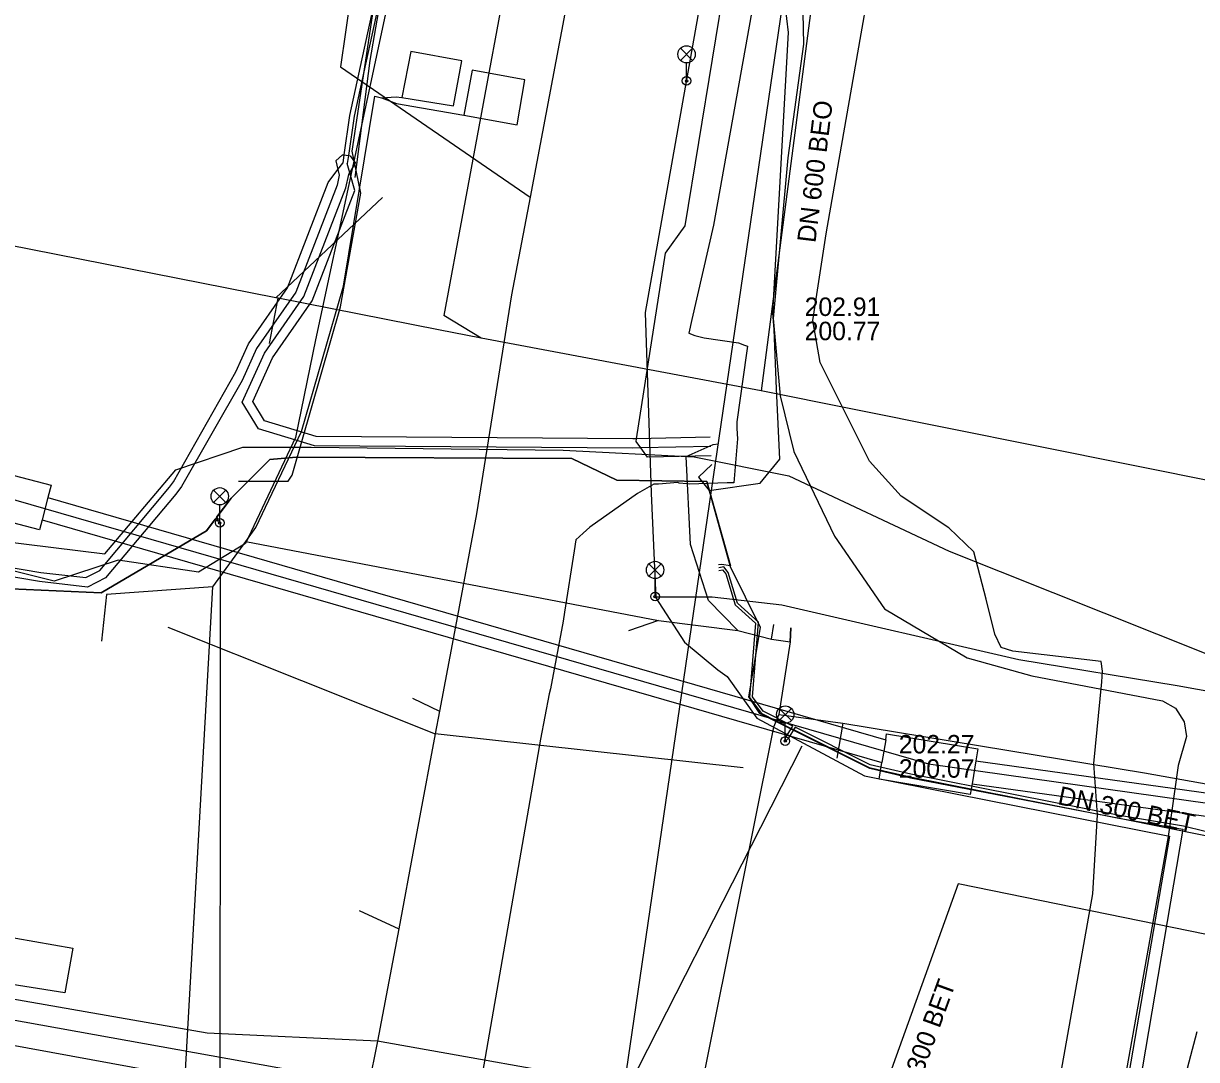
# Model space of a CAD drawing. Extents: x -596228 to -595156, y -1161235 to -1159373.
# Drawn here: x -595929.1 to -595878.3, y -1160323.7 to -1160278.8 of the extents above; entities that cross this region are included whole.
import ezdxf

# ---------------------------------------------------------------- set-up
doc = ezdxf.new("R2010")
doc.units = 0
for name, color, linetype in [('Vrstva 1', 7, 'Continuous'), ('Vrstva 10', 7, 'Continuous'), ('Vrstva 12', 7, 'Continuous'), ('Vrstva 14', 7, 'Continuous'), ('Vrstva 16', 7, 'Continuous'), ('Vrstva 19', 7, 'Continuous'), ('Vrstva 33', 7, 'Continuous'), ('Vrstva 4', 7, 'Continuous'), ('Vrstva 42', 7, 'Continuous'), ('Vrstva 44', 7, 'Continuous'), ('Vrstva 5', 7, 'Continuous'), ('Vrstva 53', 7, 'Continuous'), ('Vrstva 54', 7, 'Continuous'), ('Vrstva 55', 7, 'Continuous'), ('Vrstva 58', 7, 'Continuous'), ('Vrstva 9', 7, 'Continuous')]:
    doc.layers.add(name, color=color, linetype=linetype)

msp = doc.modelspace()

# ---------------------------------------------------------------- linework, layer by layer
at = {"layer": 'Vrstva 1'}
for p, q in [((-595903.46, -1160251.27), (-595910.91, -1160291.43)), ((-595894.35, -1160272.94), (-595897.18, -1160294.69)), ((-595913.57, -1160286.32), (-595918.179, -1160290.659)), ((-595918.462, -1160292.641), (-595918.081, -1160290.678)), ((-595909.29, -1160292.41), (-595910.91, -1160291.43)), ((-595897.18, -1160294.69), (-595909.29, -1160292.41)), ((-595854.43, -1160303.29), (-595897.18, -1160294.69)), ((-595922.85, -1160304.93), (-595911.286, -1160309.552)), ((-595897.96, -1160311.02), (-595911.286, -1160309.552)), ((-595888.65, -1160316.04), (-595892.47, -1160326.63)), ((-595888.649, -1160316.044), (-595892.47, -1160326.63)), ((-595871.84, -1160319.47), (-595888.65, -1160316.04)), ((-595871.843, -1160319.471), (-595888.65, -1160316.042)), ((-595914.57, -1160317.2), (-595912.866, -1160317.985))]:
    msp.add_line(p, q, dxfattribs=at)
msp.add_lwpolyline([(-595909.29, -1160292.41), (-595911.144, -1160292.045), (-595918.081, -1160290.678), (-595918.179, -1160290.659), (-595934.064, -1160287.531), (-595934.702, -1160287.405), (-595941.02, -1160286.161), (-595949.988, -1160284.394), (-595952.078, -1160283.983), (-595952.65, -1160283.87)], dxfattribs=at)
at = {"layer": 'Vrstva 10'}
for p, q in [((-595928.05, -1160299.31), (-595928.3, -1160300.28)), ((-595928.05, -1160299.31), (-595928.3, -1160300.28)), ((-595928.05, -1160299.31), (-595891.79, -1160309.8)), ((-595928.05, -1160299.31), (-595891.79, -1160309.8)), ((-595928.3, -1160300.28), (-595891.96, -1160310.79)), ((-595928.3, -1160300.28), (-595891.96, -1160310.79)), ((-595891.79, -1160309.8), (-595891.96, -1160310.79)), ((-595891.79, -1160309.8), (-595891.96, -1160310.79)), ((-595887.89, -1160310.72), (-595888.05, -1160311.71)), ((-595887.89, -1160310.72), (-595888.05, -1160311.71)), ((-595887.89, -1160310.72), (-595811.15, -1160321.35)), ((-595887.89, -1160310.72), (-595811.15, -1160321.35)), ((-595888.05, -1160311.71), (-595811.33, -1160322.33)), ((-595888.05, -1160311.71), (-595811.33, -1160322.33))]:
    msp.add_line(p, q, dxfattribs=at)
for points in [[(-595931.93, -1160298.34), (-595931.78, -1160297.77), (-595927.91, -1160298.77), (-595928.05, -1160299.31)], [(-595931.93, -1160298.34), (-595931.78, -1160297.77), (-595927.91, -1160298.77), (-595928.05, -1160299.31)], [(-595928.3, -1160300.28), (-595928.41, -1160300.71), (-595932.28, -1160299.7), (-595932.18, -1160299.31)], [(-595928.3, -1160300.28), (-595928.41, -1160300.71), (-595932.28, -1160299.7), (-595932.18, -1160299.31)], [(-595891.79, -1160309.8), (-595891.75, -1160309.54), (-595887.8, -1160310.2), (-595887.89, -1160310.72)], [(-595891.79, -1160309.8), (-595891.75, -1160309.54), (-595887.8, -1160310.2), (-595887.89, -1160310.72)], [(-595888.05, -1160311.71), (-595888.13, -1160312.17), (-595892.08, -1160311.51), (-595891.96, -1160310.79)], [(-595888.05, -1160311.71), (-595888.13, -1160312.17), (-595892.08, -1160311.51), (-595891.96, -1160310.79)]]:
    msp.add_lwpolyline(points, dxfattribs=at)
at = {"layer": 'Vrstva 12'}
msp.add_line((-595913.327, -1160277.82), (-595916.466, -1160292.479), dxfattribs=at)
for points in [[(-595916.466, -1160292.479), (-595917.33, -1160296.71), (-595919.49, -1160301.3), (-595921.53, -1160302.54), (-595925, -1160302.02), (-595927.78, -1160302.93), (-595932.98, -1160301.64), (-595934.44, -1160300.59), (-595934.41, -1160299.84), (-595933.92, -1160299.18)], [(-595930.09, -1160299.24), (-595889.94, -1160310.85), (-595809.314, -1160322.217)]]:
    msp.add_lwpolyline(points, dxfattribs=at)
at = {"layer": 'Vrstva 14'}
for points in [[(-595903.525, -1160327.591), (-595903.438, -1160327.11), (-595895.992, -1160276.218), (-595895.362, -1160271.913), (-595894.416, -1160266.829), (-595893.077, -1160257.958), (-595892.847, -1160256.335), (-595887.94, -1160223.167), (-595881.65, -1160186.81), (-595876.814, -1160159.541), (-595869.649, -1160117.522), (-595863.209, -1160078.856), (-595858.091, -1160048.124), (-595857.576, -1160045.207), (-595855.994, -1160045.422), (-595855.543, -1160042.523), (-595857.05, -1160042.292), (-595850.5, -1160006.311), (-595840.026, -1160007.969)], [(-595912.327, -1160326.199), (-595944.525, -1160320.296), (-595964.314, -1160316.668), (-595981.5, -1160313.518), (-595993.326, -1160311.35), (-595998.98, -1160310.314), (-596012.243, -1160307.882), (-596018.266, -1160306.788), (-596020.483, -1160306.371), (-596031.546, -1160304.536), (-596031.549, -1160304.535)]]:
    msp.add_lwpolyline(points, dxfattribs=at)
at = {"layer": 'Vrstva 16'}
msp.add_lwpolyline([(-595917.38, -1160324.14), (-595937.03, -1160320.6), (-595938.02, -1160320.43), (-595944.42, -1160319.31), (-595959.68, -1160316.64), (-595967.05, -1160315.3), (-595979.197, -1160313.085)], dxfattribs=at)
at = {"layer": 'Vrstva 19'}
msp.add_lwpolyline([(-595897.424, -1160277.35), (-595899.243, -1160287.517), (-595900.187, -1160291.609), (-595900.304, -1160292.198), (-595900.056, -1160292.292), (-595899.647, -1160292.397), (-595898.154, -1160292.619), (-595897.903, -1160292.711), (-595897.776, -1160292.755), (-595897.812, -1160293.055), (-595898.226, -1160296.041), (-595898.234, -1160296.33), (-595898.199, -1160296.768), (-595898.359, -1160298.672), (-595898.644, -1160298.671), (-595900.278, -1160298.736), (-595900.392, -1160298.713), (-595900.724, -1160298.687), (-595900.779, -1160298.661), (-595901.623, -1160298.727), (-595901.831, -1160298.727), (-595902.532, -1160299.138), (-595904.591, -1160300.602), (-595904.877, -1160300.858), (-595905.2, -1160301.147), (-595905.273, -1160301.62), (-595905.685, -1160304.282), (-595905.754, -1160304.662), (-595906.299, -1160307.601), (-595906.351, -1160307.82), (-595906.726, -1160309.776), (-595909.359, -1160324.873)], dxfattribs=at)
at = {"layer": 'Vrstva 33'}
for p, q in [((-595900.675, -1160279.855), (-595900.145, -1160280.385)), ((-595900.675, -1160280.385), (-595900.145, -1160279.855)), ((-595900.41, -1160281.27), (-595900.41, -1160280.495)), ((-595920.875, -1160298.995), (-595920.345, -1160299.525)), ((-595920.875, -1160299.525), (-595920.345, -1160298.995)), ((-595920.61, -1160300.41), (-595920.61, -1160299.635)), ((-595902.035, -1160302.185), (-595901.505, -1160302.715)), ((-595902.035, -1160302.715), (-595901.505, -1160302.185)), ((-595901.77, -1160303.6), (-595901.77, -1160302.825)), ((-595896.402, -1160308.444), (-595895.872, -1160308.974)), ((-595896.402, -1160308.974), (-595895.872, -1160308.444)), ((-595896.137, -1160309.859), (-595896.137, -1160309.084))]:
    msp.add_line(p, q, dxfattribs=at)
for centre, radius in [((-595900.41, -1160280.12), 0.375), ((-595900.41, -1160281.27), 0.19), ((-595900.41, -1160281.27), 0.05), ((-595920.61, -1160299.26), 0.375), ((-595920.61, -1160300.41), 0.19), ((-595920.61, -1160300.41), 0.05), ((-595901.77, -1160302.45), 0.375), ((-595901.77, -1160303.6), 0.19), ((-595901.77, -1160303.6), 0.05), ((-595896.137, -1160308.709), 0.375), ((-595896.137, -1160309.859), 0.19), ((-595896.137, -1160309.859), 0.05)]:
    msp.add_circle(centre, radius, dxfattribs=at)
at = {"layer": 'Vrstva 42'}
for p, q in [((-595919.369, -1160292.663), (-595917.68, -1160290.231)), ((-595917.324, -1160290.42), (-595919.02, -1160292.861)), ((-595918.67, -1160293.059), (-595916.968, -1160290.608)), ((-595918.321, -1160293.257), (-595916.612, -1160290.797)), ((-595899.257, -1160297.02), (-595899.038, -1160296.984)), ((-595925.509, -1160303.506), (-595925.725, -1160305.533)), ((-595920.903, -1160303.182), (-595925.509, -1160303.506)), ((-595901.62, -1160304.641), (-595902.915, -1160305.079)), ((-595896.735, -1160305.447), (-595896.634, -1160304.812)), ((-595895.931, -1160305.565), (-595895.894, -1160304.949)), ((-595893.65, -1160309.078), (-595893.899, -1160310.595))]:
    msp.add_line(p, q, dxfattribs=at)
for points in [[(-595899.339, -1160297.503), (-595902.099, -1160297.56), (-595902.383, -1160297.165), (-595902.586, -1160296.883), (-595902.568, -1160296.769), (-595901.316, -1160288.727), (-595900.471, -1160287.553), (-595898.687, -1160276.707), (-595898.101, -1160273.351), (-595895.17, -1160256.55), (-595893.577, -1160246.717), (-595892.781, -1160243.14), (-595887.556, -1160214.494), (-595883.249, -1160189.231), (-595883.208, -1160189), (-595882.655, -1160185.86), (-595879.849, -1160169.95), (-595878.786, -1160163.811), (-595878.313, -1160161.147), (-595878.278, -1160160.95), (-595875.884, -1160147.461), (-595871.512, -1160122.724)], [(-595899.318, -1160297.883), (-595899.891, -1160298.432), (-595899.423, -1160299.009), (-595897.224, -1160298.688), (-595896.375, -1160297.645), (-595896.521, -1160294.611), (-595896.622, -1160292.035), (-595896.678, -1160291.316), (-595895.995, -1160279.177), (-595896.207, -1160277.347), (-595896.845, -1160276.413), (-595898.101, -1160273.351), (-595898.174, -1160273.174), (-595898.37, -1160272.566), (-595895.372, -1160255.298), (-595894.03, -1160247.01), (-595893.153, -1160242.953), (-595888.976, -1160220.051), (-595884.001, -1160189.966)], [(-595918.504, -1160259.738), (-595913.263, -1160260.629), (-595911.808, -1160260.75), (-595911.519, -1160260.809), (-595911.298, -1160261.051), (-595910.768, -1160262.017), (-595910.821, -1160262.872), (-595911.242, -1160265.118), (-595912.672, -1160273.05), (-595914.792, -1160282.798), (-595915.041, -1160284.502), (-595915.041, -1160284.504), (-595915.091, -1160284.854)], [(-595918.537, -1160259.935), (-595913.288, -1160260.828), (-595911.837, -1160260.948), (-595911.623, -1160260.992), (-595911.462, -1160261.169), (-595910.972, -1160262.063), (-595911.019, -1160262.848), (-595911.438, -1160265.082), (-595912.868, -1160273.011), (-595914.988, -1160282.762), (-595915.239, -1160284.476), (-595915.239, -1160284.478), (-595915.289, -1160284.826)], [(-595913.609, -1160282.001), (-595912.971, -1160281.955), (-595912.73, -1160281.991), (-595910.501, -1160282.355), (-595910.13, -1160280.397), (-595912.345, -1160279.993), (-595912.73, -1160281.991)], [(-595913.609, -1160282.001), (-595912.965, -1160282.254), (-595910.043, -1160282.754), (-595907.746, -1160283.177), (-595907.407, -1160281.223), (-595909.682, -1160280.812), (-595910.043, -1160282.754)], [(-595919.478, -1160301.216), (-595919.042, -1160300.616), (-595917.066, -1160296.454), (-595915.261, -1160290.166), (-595913.904, -1160281.938), (-595913.609, -1160282.001)], [(-595915.58, -1160284.73), (-595915.495, -1160285.101), (-595915.436, -1160285.356), (-595915.533, -1160285.782), (-595917.324, -1160290.42)], [(-595915.58, -1160284.73), (-595915.3, -1160284.47), (-595915.239, -1160284.478), (-595915.14, -1160284.49), (-595915.041, -1160284.502), (-595914.97, -1160284.51), (-595914.73, -1160284.84)], [(-595917.68, -1160290.231), (-595915.918, -1160285.668), (-595915.495, -1160285.101), (-595915.289, -1160284.826)], [(-595916.968, -1160290.608), (-595915.149, -1160285.896), (-595915.03, -1160285.329), (-595914.98, -1160285.248), (-595914.73, -1160284.84)], [(-595916.612, -1160290.797), (-595914.764, -1160286.01), (-595914.98, -1160285.248), (-595915.091, -1160284.854)], [(-595970.95, -1160294.68), (-595969.41, -1160294.83), (-595963.368, -1160295.921), (-595949.631, -1160298.537), (-595937.889, -1160300.943), (-595928.355, -1160302.554), (-595926.404, -1160302.777), (-595925.807, -1160302.472), (-595922.787, -1160298.86), (-595922.611, -1160298.637), (-595919.917, -1160293.875), (-595919.369, -1160292.663)], [(-595919.02, -1160292.861), (-595919.646, -1160294.248), (-595922.262, -1160298.834), (-595922.517, -1160299.16), (-595925.553, -1160302.79), (-595926.33, -1160303.189), (-595928.411, -1160302.95), (-595937.955, -1160301.337)], [(-595899.361, -1160297.104), (-595902.383, -1160297.165), (-595902.741, -1160297.172), (-595916.503, -1160297.069), (-595918.929, -1160296.336), (-595919.633, -1160295.189), (-595918.67, -1160293.059)], [(-595899.384, -1160296.705), (-595902.568, -1160296.769), (-595902.739, -1160296.772), (-595916.443, -1160296.669), (-595918.667, -1160295.998), (-595919.181, -1160295.161), (-595918.321, -1160293.257)], [(-595943.26, -1160323.541), (-595943.78, -1160322.58), (-595940.91, -1160302.02), (-595939.31, -1160301.1), (-595930.15, -1160301.19), (-595925.58, -1160301.75), (-595922.51, -1160298.12), (-595919.61, -1160297.13), (-595916.66, -1160297.13), (-595905.75, -1160297.26), (-595900.08, -1160297.55), (-595895.98, -1160298.37), (-595889.04, -1160301.63), (-595877.87, -1160306.09), (-595875.35, -1160307.92), (-595868.01, -1160309.1), (-595862.33, -1160310.88), (-595847.13, -1160313.44), (-595833.42, -1160315.69)], [(-595943.26, -1160323.541), (-595943.78, -1160322.58), (-595940.91, -1160302.02), (-595939.31, -1160301.1), (-595930.15, -1160301.19), (-595925.58, -1160301.75), (-595922.51, -1160298.12), (-595919.61, -1160297.13), (-595916.66, -1160297.13), (-595905.75, -1160297.26), (-595900.08, -1160297.55), (-595895.98, -1160298.37), (-595889.04, -1160301.63), (-595877.87, -1160306.09), (-595875.35, -1160307.92), (-595868.01, -1160309.1), (-595862.33, -1160310.88), (-595847.13, -1160313.44), (-595833.42, -1160315.69)], [(-595943.26, -1160323.541), (-595943.78, -1160322.58), (-595940.91, -1160302.02), (-595939.31, -1160301.1), (-595930.15, -1160301.19), (-595925.58, -1160301.75), (-595922.51, -1160298.12), (-595919.61, -1160297.13), (-595916.66, -1160297.13), (-595905.75, -1160297.26), (-595900.08, -1160297.55), (-595895.98, -1160298.37), (-595889.04, -1160301.63), (-595877.87, -1160306.09), (-595875.35, -1160307.92), (-595868.01, -1160309.1), (-595862.33, -1160310.88), (-595847.13, -1160313.44), (-595833.42, -1160315.69)], [(-595943.26, -1160323.541), (-595943.78, -1160322.58), (-595940.91, -1160302.02), (-595939.31, -1160301.1), (-595930.15, -1160301.19), (-595925.58, -1160301.75), (-595922.51, -1160298.12), (-595919.61, -1160297.13), (-595916.66, -1160297.13), (-595905.75, -1160297.26), (-595900.08, -1160297.55), (-595895.98, -1160298.37), (-595889.04, -1160301.63), (-595877.87, -1160306.09), (-595875.35, -1160307.92), (-595868.01, -1160309.1), (-595862.33, -1160310.88), (-595847.13, -1160313.44), (-595833.42, -1160315.69)], [(-595943.78, -1160322.58), (-595940.91, -1160302.02), (-595939.31, -1160301.1), (-595930.15, -1160301.19), (-595925.58, -1160301.75), (-595922.51, -1160298.12), (-595919.61, -1160297.13), (-595916.66, -1160297.13), (-595905.75, -1160297.26), (-595900.08, -1160297.55), (-595895.98, -1160298.37), (-595889.04, -1160301.63), (-595877.87, -1160306.09), (-595875.35, -1160307.92), (-595876.03, -1160312.35), (-595876.906, -1160312.977)], [(-595943.78, -1160322.58), (-595940.91, -1160302.02), (-595939.31, -1160301.1), (-595930.15, -1160301.19), (-595925.58, -1160301.75), (-595922.51, -1160298.12), (-595919.61, -1160297.13), (-595916.66, -1160297.13), (-595905.75, -1160297.26), (-595900.08, -1160297.55), (-595895.98, -1160298.37), (-595889.04, -1160301.63), (-595877.87, -1160306.09), (-595875.35, -1160307.92), (-595876.03, -1160312.35), (-595876.906, -1160312.977)], [(-595898.195, -1160305.065), (-595899.465, -1160303.777), (-595900.233, -1160301.35), (-595900.43, -1160297.538), (-595899.257, -1160297.02)], [(-595932.932, -1160324.581), (-595929.027, -1160325.242), (-595923.071, -1160326.404), (-595922.307, -1160327.96), (-595920.903, -1160303.182), (-595919.478, -1160301.216), (-595901.62, -1160304.641), (-595898.195, -1160305.065), (-595896.735, -1160305.447), (-595895.931, -1160305.565), (-595896.41, -1160308.706), (-595896.64, -1160309.26), (-595901.111, -1160331.564), (-595901.699, -1160330.991), (-595905.91, -1160330.801), (-595909.662, -1160330.217), (-595910.286, -1160331.011), (-595911.466, -1160332.883), (-595912.47, -1160339.95), (-595912.872, -1160339.865)], [(-595895.894, -1160304.949), (-595895.931, -1160305.565), (-595896.41, -1160308.706), (-595893.65, -1160309.078), (-595880.587, -1160311.231), (-595867.748, -1160313.527), (-595860.217, -1160314.981), (-595847.991, -1160316.922), (-595834.216, -1160319.371), (-595820.364, -1160321.5), (-595806.264, -1160323.708), (-595792.142, -1160326.114), (-595783.529, -1160327.233), (-595777.032, -1160326.773), (-595764.779, -1160324.315), (-595754.282, -1160321.569), (-595753.606, -1160323.921), (-595750.637, -1160332.868), (-595750.632, -1160333.38), (-595740.462, -1160333.548), (-595739.673, -1160332.748), (-595739.749, -1160331.939)], [(-595896.41, -1160308.706), (-595893.65, -1160309.078), (-595880.587, -1160311.231), (-595867.748, -1160313.527), (-595860.217, -1160314.981), (-595861.066, -1160316.276), (-595861.82, -1160316.751)], [(-595932.932, -1160324.581), (-595932.885, -1160324.298), (-595932.877, -1160323.754), (-595932.247, -1160319.983), (-595931.921, -1160317.962), (-595926.975, -1160318.829), (-595927.32, -1160320.768), (-595932.247, -1160319.983)]]:
    msp.add_lwpolyline(points, dxfattribs=at)
at = {"layer": 'Vrstva 44'}
msp.add_lwpolyline([(-595895.399, -1160276.958), (-595895.348, -1160279.684), (-595896.029, -1160284.609), (-595896.664, -1160291.553), (-595896.355, -1160294.907), (-595895.764, -1160297.318), (-595894.012, -1160300.979), (-595891.845, -1160304.138), (-595888.262, -1160306.26), (-595885.467, -1160307.035), (-595879.806, -1160308.12), (-595879.242, -1160308.43), (-595878.869, -1160309.022), (-595878.777, -1160309.66), (-595879.139, -1160310.91), (-595879.564, -1160313.987), (-595883.002, -1160333.198)], dxfattribs=at)
at = {"layer": 'Vrstva 5'}
for p, q in [((-595911.59, -1160253.94), (-595915.382, -1160280.667)), ((-595915.382, -1160280.667), (-595907.181, -1160286.303))]:
    msp.add_line(p, q, dxfattribs=at)
at = {"layer": 'Vrstva 53'}
msp.add_lwpolyline([(-595910.39, -1160257.27), (-595910.65, -1160259.73), (-595910.78, -1160261.08), (-595912.45, -1160270.8), (-595914.12, -1160280.39), (-595914.76, -1160285.45)], dxfattribs=at)
at = {"layer": 'Vrstva 54'}
for p, q in [((-595920.58, -1160309.17), (-595920.58, -1160300.4)), ((-595920.59, -1160330.87), (-595920.58, -1160309.17)), ((-595897.2, -1160313.58), (-595895.41, -1160310.06)), ((-595905.35, -1160329.62), (-595897.2, -1160313.58)), ((-595879.08, -1160325.37), (-595878.31, -1160322.44))]:
    msp.add_line(p, q, dxfattribs=at)
at = {"layer": 'Vrstva 55'}
for points in [[(-595901.722, -1160303.649), (-595901.92, -1160299.12), (-595902.19, -1160291.297), (-595890.66, -1160226.32), (-595886.19, -1160198.97), (-595881.04, -1160171.41), (-595876.29, -1160143.99), (-595871.58, -1160116.92), (-595868.39, -1160099.39), (-595861.162, -1160062.826), (-595862.06, -1160062.41)], [(-595901.76, -1160303.617), (-595899.3, -1160303.61), (-595896.29, -1160303.96), (-595886.03, -1160306.33), (-595879.17, -1160307.45), (-595874.21, -1160308.35), (-595868.67, -1160308.9), (-595866.48, -1160309.64), (-595862.38, -1160310.3), (-595857.55, -1160310.83), (-595856.39, -1160310.83), (-595847.78, -1160303.22), (-595848.19, -1160302.21), (-595848.33, -1160301.9), (-595850.06, -1160300.47), (-595850.11, -1160299.93), (-595845.38, -1160295.57), (-595833.73, -1160286.06)], [(-595929.63, -1160303.27), (-595925.74, -1160303.44), (-595921.19, -1160300.75), (-595920.806, -1160300.244), (-595920.66, -1160300.33), (-595920.731, -1160300.146), (-595920.12, -1160299.34), (-595918.45, -1160297.66), (-595917.31, -1160297.56), (-595905.37, -1160297.62), (-595903.42, -1160298.56), (-595899.53, -1160298.62), (-595898.51, -1160302.27), (-595898.89, -1160302.212), (-595899.02, -1160302.233)], [(-595899.01, -1160302.475), (-595898.851, -1160302.449), (-595898.714, -1160302.619), (-595898.303, -1160303.953), (-595897.422, -1160304.755), (-595897.682, -1160307.978), (-595897.18, -1160308.657), (-595895.88, -1160309.31), (-595895.773, -1160309.364), (-595892.5, -1160311.007), (-595890.732, -1160311.409), (-595881.701, -1160313.199), (-595878.928, -1160313.669), (-595882.299, -1160333.495), (-595901.158, -1160330.111), (-595905.425, -1160329.09), (-595905.669, -1160331.811)], [(-595877.97, -1160313.77), (-595878.908, -1160313.55), (-595881.679, -1160313.081), (-595890.708, -1160311.291), (-595892.46, -1160310.893), (-595895.715, -1160309.259), (-595896.005, -1160309.751), (-595896.14, -1160309.86), (-595896.108, -1160309.689), (-595895.813, -1160309.208), (-595897.1, -1160308.563), (-595897.558, -1160307.942), (-595897.298, -1160304.705), (-595898.197, -1160303.887), (-595898.606, -1160302.561), (-595898.802, -1160302.319), (-595899.015, -1160302.354)], [(-595901.76, -1160303.617), (-595900.5, -1160305.57), (-595899.058, -1160306.768), (-595898.651, -1160307.058), (-595897.37, -1160308.863), (-595892.714, -1160311.365), (-595879.502, -1160313.984), (-595882.762, -1160333.016), (-595905.518, -1160329.407), (-595905.751, -1160332.201)]]:
    msp.add_lwpolyline(points, dxfattribs=at)
at = {"layer": 'Vrstva 58'}
for points in [[(-595919.8, -1160298.61), (-595917.65, -1160298.61), (-595917.47, -1160298.35), (-595915.38, -1160291.05), (-595914.51, -1160286.13), (-595914.88, -1160284.32), (-595913.96, -1160278.16), (-595912.99, -1160273.19), (-595911.12, -1160261.2)], [(-595891.44, -1160334.1), (-595886.33, -1160335.16), (-595885.22, -1160329.96), (-595882.82, -1160316.47), (-595882.62, -1160313.06), (-595882.78, -1160310.83), (-595882.43, -1160307.29), (-595882.41, -1160306.83), (-595882.47, -1160306.41), (-595886.29, -1160305.97), (-595886.8, -1160305.8), (-595887.07, -1160305.23), (-595887.44, -1160303.71), (-595887.97, -1160301.67), (-595889.06, -1160300.62), (-595891.12, -1160299.25), (-595892.49, -1160297.74), (-595894.63, -1160293.46), (-595894.95, -1160291.64), (-595894.36, -1160287.89), (-595892.89, -1160279.48), (-595889.65, -1160261.01)], [(-595885.22, -1160329.96), (-595882.82, -1160316.47), (-595882.62, -1160313.06), (-595882.78, -1160310.83), (-595882.43, -1160307.29), (-595882.41, -1160306.83), (-595882.47, -1160306.41), (-595886.29, -1160305.97), (-595886.8, -1160305.8), (-595887.07, -1160305.23), (-595887.44, -1160303.71), (-595887.97, -1160301.67), (-595889.06, -1160300.62), (-595891.12, -1160299.25), (-595892.49, -1160297.74), (-595894.63, -1160293.46), (-595894.95, -1160291.64), (-595894.36, -1160287.89), (-595892.89, -1160279.48), (-595889.65, -1160261.01)], [(-595877.95, -1160313.96), (-595881.67, -1160313.21), (-595890.71, -1160311.46), (-595892.48, -1160311.04), (-595897.24, -1160308.67), (-595897.72, -1160307.95), (-595897.21, -1160304.94), (-595898.5, -1160302.32), (-595899.53, -1160298.62), (-595903.42, -1160298.56), (-595905.37, -1160297.62), (-595917.31, -1160297.56), (-595918.45, -1160297.66), (-595920.12, -1160299.34), (-595921.19, -1160300.75), (-595925.74, -1160303.44), (-595929.63, -1160303.27)]]:
    msp.add_lwpolyline(points, dxfattribs=at)
at = {"layer": 'Vrstva 9'}
for p, q in [((-595907.98, -1160290.528), (-595909.5, -1160300.02)), ((-595912.273, -1160308.007), (-595911.1, -1160308.559)), ((-595913.78, -1160322.86), (-595921.15, -1160322.51)), ((-595913.78, -1160322.86), (-595915.27, -1160330.17)), ((-595892.47, -1160326.63), (-595913.78, -1160322.86))]:
    msp.add_line(p, q, dxfattribs=at)
for points in [[(-595902.77, -1160262.96), (-595907.181, -1160286.303), (-595907.98, -1160290.528)], [(-595909.5, -1160300.02), (-595910.414, -1160304.895), (-595911.1, -1160308.559), (-595911.286, -1160309.552), (-595911.994, -1160313.328), (-595912.18, -1160314.321), (-595912.866, -1160317.985), (-595913.78, -1160322.86)], [(-595921.15, -1160322.51), (-595945.757, -1160318.202), (-595957.25, -1160316.19)]]:
    msp.add_lwpolyline(points, dxfattribs=at)

# ---------------------------------------------------------------- texts
at = {"layer": 'Vrstva 4'}
for s, rotation, p in [('DN 600 BEO', 83, (-595894.831, -1160288.307)), ('DN 300 BET', 348, (-595884.382, -1160312.586)), ('DN 300 BET', 70, (-595890.807, -1160326.016))]:
    msp.add_text(s, height=0.8, rotation=rotation, dxfattribs=at).set_placement(p)
for s, p in [('202.91', (-595895.296, -1160291.45)), ('200.77', (-595895.296, -1160292.5)), ('202.27', (-595891.223, -1160310.395)), ('200.07', (-595891.223, -1160311.445))]:
    msp.add_text(s, height=0.8, dxfattribs=at).set_placement(p)

doc.saveas('drawing.dxf')
